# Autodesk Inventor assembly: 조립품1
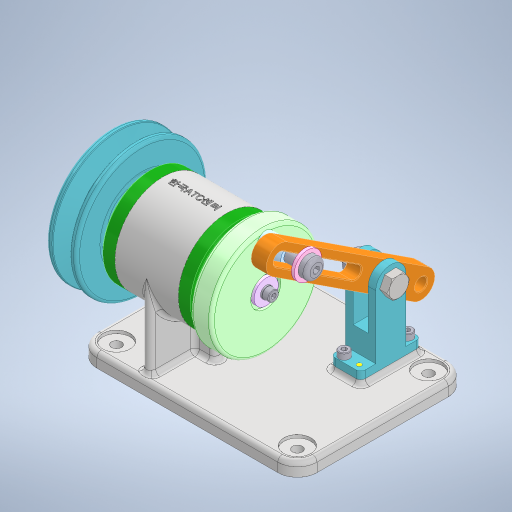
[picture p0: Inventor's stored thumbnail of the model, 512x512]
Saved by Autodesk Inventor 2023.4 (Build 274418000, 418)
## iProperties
Created: 2024-07
Part Number: 조립품1
Document SubType Name: Assembly
Designer: EDU
Mass: 1033.55 g
Surface Area: 1663.58 cm^2
Volume: 499.558 cm^3
Density: 2.06893 g/cm^3
Author: EDU
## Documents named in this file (25)
- C:\Users\EDU\Desktop\640704V1005\조립품1.iam
- C:\Users\EDU\Desktop\평행키 5x5x12\평행키 5x5x12.ipt
- C:\Users\EDU\Desktop\핀 3 x 8\핀 3 x 8.ipt
- C:\Users\EDU\Desktop\힌지 축\힌지 축.ipt
- C:\Users\EDU\Desktop\힌지\힌지.ipt
- C:\Users\EDU\Desktop\V-벨트풀리\V-벨트풀리.ipt
- C:\Users\EDU\Desktop\돌림판\돌림판.ipt
- C:\Users\EDU\Desktop\베어링 6004\베어링 6004.ipt
- C:\Users\EDU\Desktop\본체\본체.ipt
- C:\Users\EDU\Desktop\스트리퍼 볼트 8 x 30\스트리퍼 볼트 8 x 30.ipt
- C:\Users\EDU\Desktop\스페이서\스페이서.ipt
- C:\Users\EDU\Desktop\스프링 와셔 M4\스프링 와셔 M4.ipt
- C:\Users\EDU\Desktop\앤드 캡\앤드 캡.ipt
- C:\Users\EDU\Desktop\오일 실 20 32 5\오일 실 20 32 5.ipt
- C:\Users\EDU\Desktop\육각 너트 M8\육각 너트 M8.ipt
- C:\Users\EDU\Desktop\육각 너트 M10x1\육각 너트 M10x1.ipt
- C:\Users\EDU\Desktop\육각 소켓 머리 볼트 M4x10\육각 소켓 머리 볼트 M4x10.ipt
- C:\Users\EDU\Desktop\축\축.ipt
- C:\Users\EDU\Desktop\커버\커버.ipt
- C:\Users\EDU\Desktop\크랭크\크랭크.ipt
- C:\Users\EDU\Desktop\평와셔 M8\평와셔 M8.ipt
- C:\Users\EDU\Desktop\평와셔 M10\평와셔 M10.ipt
- C:\Users\EDU\Desktop\평행키 4x4x8\평행키 4x4x8.ipt
- C:\Users\EDU\Desktop\640704V1005\육각 소켓 머리 볼트 M4x10\육각 소켓 머리 볼트 M4x10.ipt
- C:\Users\EDU\Desktop\640704V1005\칼라\칼라.ipt
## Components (3 placed, 2 different names)
1. 핀 3 x 8:1 — 플러쉬:3
2. V-벨트풀리:1 — 플러쉬:1, 각도:2
3. 핀 3 x 8:2 — 플러쉬:4
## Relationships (4: Flush 3, Angle 1)
- 플러쉬:1 [Flush]: V-벨트풀리:1
- 플러쉬:3 [Flush]: 핀 3 x 8:1
- 플러쉬:4 [Flush]: 핀 3 x 8:2
- 각도:2 [Angle]: V-벨트풀리:1
